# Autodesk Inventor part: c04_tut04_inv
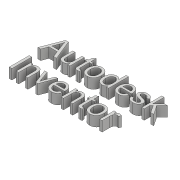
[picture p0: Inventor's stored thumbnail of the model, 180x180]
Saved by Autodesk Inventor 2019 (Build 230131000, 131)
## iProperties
Created: 2017-04
Part Number: c04_tut04_inv
Material: Generic
Document SubType Name: Modeling
Designer: CADCIM 00
Density: 1 g/cm^3
Appearance: Default
Author: CADCIM 00
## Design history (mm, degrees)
sketch "Sketch1"
  geometry: L1 (0.506, 21.792)-(30.182, 21.792); L2 (30.182, 21.792)-(30.182, 9.249); L3 (30.182, 9.249)-(0.506, 9.249); L4 (0.506, 9.249)-(0.506, 21.792); 1 further point
  constraints: 2 other
extrude "Extrusion1" new body sketch "Sketch1" distance "d0" = 2.5; taper "d1" = 0 deg
body "Solid1"
